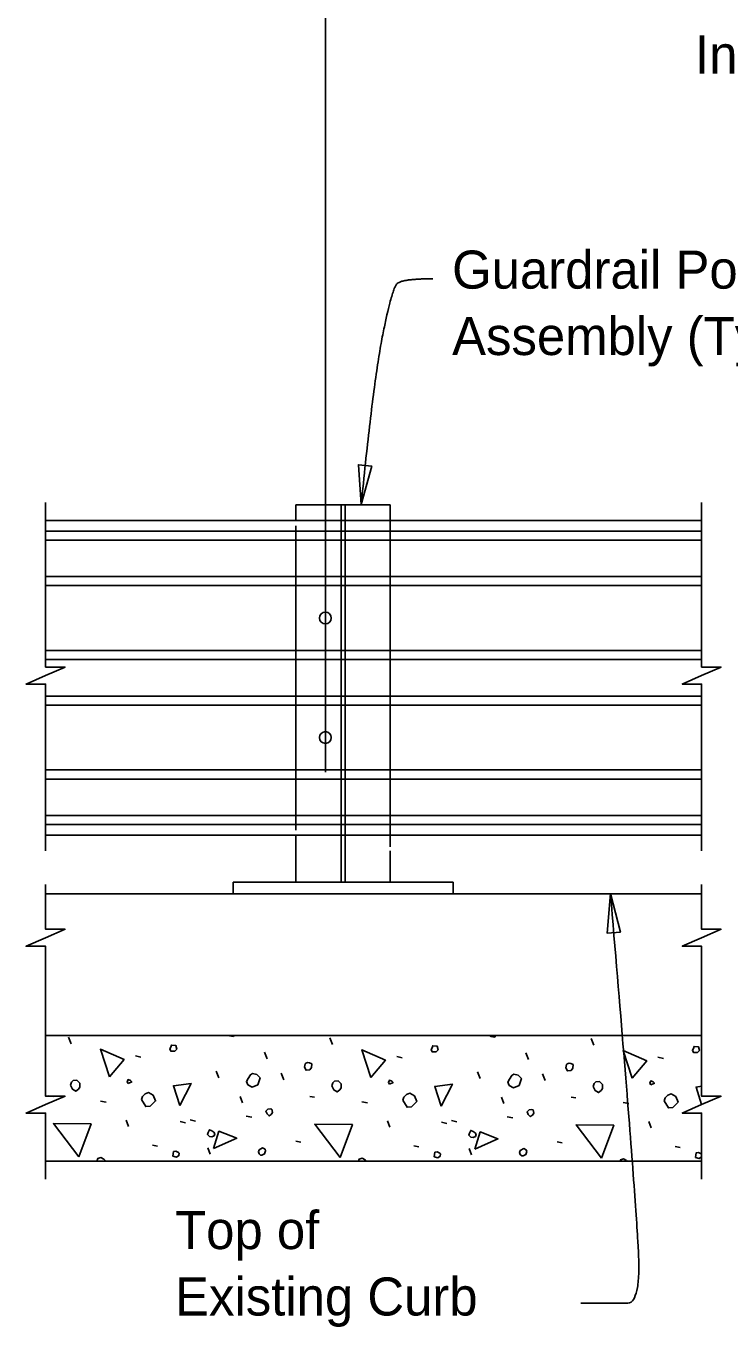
# Model space of a CAD drawing. Extents: x 21516.9 to 21589, y 56155.1 to 56195.
# Drawn here: x 21519.8 to 21523.53, y 56169.36 to 56176.26 of the extents above; entities that cross this region are included whole.
import ezdxf

# ---------------------------------------------------------------- set-up
doc = ezdxf.new("R2010")
doc.units = 0
for name, color, linetype in [('AdhocPoint_dp', 7, 'Continuous'), ('Border', 7, 'Continuous'), ('Patterning', 7, 'Continuous'), ('PlotBorder_dp', 7, 'Continuous'), ('TextMisc', 7, 'Continuous')]:
    doc.layers.add(name, color=color, linetype=linetype)

msp = doc.modelspace()

# ---------------------------------------------------------------- linework, layer by layer
at = {"layer": 'AdhocPoint_dp'}
for p, q in [((21523.3791, 56171.6541), (21519.9023, 56171.6541)), ((21519.9023, 56170.9041), (21523.3791, 56170.9041)), ((21523.3791, 56170.2374), (21519.9023, 56170.2374))]:
    msp.add_line(p, q, dxfattribs=at)
at = {"layer": 'Border'}
for p, q in [((21521.4686, 56171.7167), (21521.4686, 56173.7167)), ((21521.4894, 56171.7167), (21521.4894, 56173.7167)), ((21521.729, 56173.7167), (21521.729, 56171.9037)), ((21521.229, 56173.6048), (21521.229, 56171.9929))]:
    msp.add_line(p, q, dxfattribs=at)
at = {"layer": 'Patterning'}
for p, q in [((21521.229, 56173.7167), (21521.729, 56173.7167)), ((21521.229, 56173.7167), (21521.229, 56173.6334)), ((21519.9023, 56173.6333), (21523.3791, 56173.6333)), ((21519.9023, 56171.9666), (21523.3791, 56171.9666)), ((21521.229, 56171.9667), (21521.229, 56171.7167)), ((21521.729, 56171.8834), (21521.729, 56171.7167)), ((21520.8957, 56171.7167), (21522.0623, 56171.7167)), ((21520.8957, 56171.6542), (21520.8957, 56171.7167)), ((21521.229, 56171.7167), (21521.729, 56171.7167)), ((21522.0623, 56171.7167), (21522.0623, 56171.6542)), ((21520.8957, 56171.6542), (21522.0623, 56171.6542))]:
    msp.add_line(p, q, dxfattribs=at)
for centre in [(21521.3853, 56173.1166), (21521.3853, 56172.4835)]:
    msp.add_circle(centre, 0.0312, dxfattribs=at)
at = {"layer": 'PlotBorder_dp'}
msp.add_line((21521.3853, 56172.3005), (21521.3853, 56186.8174), dxfattribs=at)
for points in [[(21521.5749, 56173.7186), (21521.6306, 56173.9223), (21521.5604, 56173.9293)], [(21522.8958, 56171.6569), (21522.8782, 56171.4464), (21522.9485, 56171.4524)]]:
    msp.add_lwpolyline(points, close=True, dxfattribs=at)
for points in [[(21519.9023, 56171.8836), (21519.9023, 56172.7668), (21519.7989, 56172.7668), (21519.9023, 56172.8118), (21520.0056, 56172.8568), (21519.9023, 56172.8568), (21519.9023, 56173.7298)], [(21523.3791, 56171.8836), (21523.3791, 56172.7668), (21523.2758, 56172.7668), (21523.3791, 56172.8118), (21523.4824, 56172.8568), (21523.3791, 56172.8568), (21523.3791, 56173.7298)], [(21519.9023, 56170.9068), (21519.9023, 56171.3768), (21519.7989, 56171.3768), (21519.9023, 56171.4218), (21520.0056, 56171.4668), (21519.9023, 56171.4668), (21519.9023, 56171.7042)], [(21523.3791, 56170.9068), (21523.3791, 56171.3768), (21523.2758, 56171.3768), (21523.3791, 56171.4218), (21523.4824, 56171.4668), (21523.3791, 56171.4668), (21523.3791, 56171.7042)], [(21519.9023, 56170.1417), (21519.9023, 56170.4923), (21519.7989, 56170.4923), (21519.9023, 56170.5373), (21520.0056, 56170.5823), (21519.9023, 56170.5823), (21519.9023, 56170.9068)], [(21523.3791, 56170.1417), (21523.3791, 56170.4923), (21523.2758, 56170.4923), (21523.3791, 56170.5373), (21523.4824, 56170.5823), (21523.3791, 56170.5823), (21523.3791, 56170.9068)]]:
    msp.add_lwpolyline(points, dxfattribs=at)
for points in [[(21521.9541, 56174.9151), (21521.7906, 56174.9151), (21521.7383, 56174.8627), (21521.6402, 56174.3753), (21521.5749, 56173.7186)], [(21522.7388, 56169.4848), (21522.922, 56169.4848), (21523.0462, 56169.4848), (21523.0462, 56169.8773), (21522.8958, 56171.6569)]]:
    msp.add_open_spline(points, degree=2, dxfattribs=at)
at = {"layer": 'TextMisc'}
for p, q in [((21523.3791, 56173.5778), (21519.9023, 56173.5778)), ((21523.3791, 56173.5295), (21519.9023, 56173.5295)), ((21523.3791, 56173.3367), (21519.9023, 56173.3367)), ((21523.3791, 56173.2885), (21519.9023, 56173.2885)), ((21523.3791, 56172.9445), (21519.9023, 56172.9445)), ((21523.3791, 56172.8963), (21519.9023, 56172.8963)), ((21523.3791, 56172.7035), (21519.9023, 56172.7035)), ((21523.3791, 56172.6554), (21519.9023, 56172.6554)), ((21523.3791, 56172.3114), (21519.9023, 56172.3114)), ((21523.3791, 56172.2632), (21519.9023, 56172.2632)), ((21523.3791, 56172.0704), (21519.9023, 56172.0704)), ((21523.3791, 56172.0221), (21519.9023, 56172.0221)), ((21520.0378, 56170.8592), (21520.0236, 56170.8946)), ((21521.4224, 56170.8557), (21521.4083, 56170.891)), ((21522.8071, 56170.8521), (21522.793, 56170.8875)), ((21520.3783, 56170.7967), (21520.4066, 56170.7896)), ((21521.0766, 56170.7808), (21521.0624, 56170.8161)), ((21521.763, 56170.7932), (21521.7913, 56170.7861)), ((21522.4613, 56170.7773), (21522.4471, 56170.8126)), ((21523.1477, 56170.7896), (21523.176, 56170.7826)), ((21520.8203, 56170.68), (21520.8061, 56170.7154)), ((21521.1644, 56170.6683), (21521.1502, 56170.7036)), ((21522.2049, 56170.6765), (21522.1908, 56170.7118)), ((21522.549, 56170.6647), (21522.5349, 56170.7001)), ((21519.9176, 56170.5834), (21519.9423, 56170.5799)), ((21520.1933, 56170.5551), (21520.2234, 56170.5498)), ((21520.9458, 56170.5474), (21520.9334, 56170.581)), ((21521.3022, 56170.5799), (21521.327, 56170.5764)), ((21521.578, 56170.5516), (21521.6081, 56170.5463)), ((21522.3305, 56170.5439), (21522.3181, 56170.5775)), ((21522.6869, 56170.5764), (21522.7117, 56170.5728)), ((21522.9627, 56170.5481), (21522.9927, 56170.5428)), ((21520.9646, 56170.4756), (21520.9946, 56170.4703)), ((21520.3418, 56170.4208), (21520.3295, 56170.4544)), ((21520.6158, 56170.4473), (21520.6441, 56170.4402)), ((21520.6682, 56170.4573), (21520.6965, 56170.4502)), ((21521.7265, 56170.4173), (21521.7141, 56170.4508)), ((21522.0005, 56170.4438), (21522.0288, 56170.4367)), ((21522.0529, 56170.4538), (21522.0812, 56170.4467)), ((21522.3493, 56170.4721), (21522.3793, 56170.4668)), ((21523.1112, 56170.4137), (21523.0988, 56170.4473)), ((21521.228, 56170.343), (21521.2545, 56170.3377)), ((21522.6127, 56170.3395), (21522.6392, 56170.3342)), ((21520.4691, 56170.3218), (21520.4956, 56170.3165)), ((21520.7743, 56170.2747), (21520.7619, 56170.3083)), ((21521.8538, 56170.3183), (21521.8803, 56170.313)), ((21522.159, 56170.2712), (21522.1466, 56170.3047)), ((21523.2385, 56170.3147), (21523.265, 56170.3094))]:
    msp.add_line(p, q, dxfattribs=at)
for points in [[(21520.8761, 56170.9041), (21520.8768, 56170.9028), (21520.898, 56170.8992), (21520.9008, 56170.9041)], [(21522.2588, 56170.9041), (21522.2615, 56170.8992), (21522.2827, 56170.8957), (21522.2874, 56170.9041)], [(21520.2411, 56170.6842), (21520.1933, 56170.8309), (21520.3188, 56170.7761), (21520.2411, 56170.6842)], [(21520.5657, 56170.8214), (21520.5869, 56170.8214), (21520.5975, 56170.8321), (21520.5922, 56170.8515), (21520.5692, 56170.8533), (21520.5657, 56170.8427), (21520.5604, 56170.8338), (21520.5657, 56170.8214), (21520.5622, 56170.825)], [(21521.6257, 56170.6807), (21521.578, 56170.8274), (21521.7035, 56170.7726), (21521.6257, 56170.6807)], [(21521.9504, 56170.8179), (21521.9716, 56170.8179), (21521.9822, 56170.8285), (21521.9769, 56170.848), (21521.9539, 56170.8497), (21521.9504, 56170.8391), (21521.9451, 56170.8303), (21521.9504, 56170.8179), (21521.9468, 56170.8214)], [(21523.0104, 56170.6771), (21522.9627, 56170.8238), (21523.0882, 56170.769), (21523.0104, 56170.6771)], [(21523.3351, 56170.8144), (21523.3563, 56170.8144), (21523.3669, 56170.825), (21523.3616, 56170.8444), (21523.3386, 56170.8462), (21523.3351, 56170.8356), (21523.3298, 56170.8268), (21523.3351, 56170.8144), (21523.3315, 56170.8179)], [(21521.274, 56170.7355), (21521.2828, 56170.7195), (21521.3022, 56170.7213), (21521.3111, 56170.7337), (21521.3128, 56170.7531), (21521.3005, 56170.7584), (21521.2916, 56170.7602), (21521.281, 56170.7567), (21521.2775, 56170.7531), (21521.274, 56170.7355)], [(21522.6586, 56170.7319), (21522.6675, 56170.716), (21522.6869, 56170.7178), (21522.6958, 56170.7302), (21522.6975, 56170.7496), (21522.6851, 56170.7549), (21522.6763, 56170.7567), (21522.6657, 56170.7531), (21522.6622, 56170.7496), (21522.6586, 56170.7319)], [(21520.9741, 56170.6429), (21520.997, 56170.6305), (21521.0271, 56170.6429), (21521.0395, 56170.68), (21521.0218, 56170.6977), (21520.9988, 56170.703), (21520.9882, 56170.6959), (21520.9758, 56170.6765), (21520.967, 56170.6606), (21520.9741, 56170.6429)], [(21522.3587, 56170.6394), (21522.3817, 56170.627), (21522.4118, 56170.6394), (21522.4241, 56170.6765), (21522.4065, 56170.6942), (21522.3835, 56170.6995), (21522.3729, 56170.6924), (21522.3605, 56170.673), (21522.3517, 56170.657), (21522.3587, 56170.6394)], [(21520.0342, 56170.64), (21520.0448, 56170.6188), (21520.0625, 56170.6082), (21520.0767, 56170.6188), (21520.0837, 56170.6294), (21520.0837, 56170.6506), (21520.0678, 56170.6665), (21520.0484, 56170.6647), (21520.0395, 56170.6559), (21520.0342, 56170.64)], [(21520.3401, 56170.6488), (21520.3595, 56170.6577), (21520.3524, 56170.6647), (21520.3401, 56170.67), (21520.3348, 56170.6577), (21520.3401, 56170.6488)], [(21520.6134, 56170.5333), (21520.5798, 56170.6376), (21520.6735, 56170.65), (21520.6134, 56170.5333)], [(21521.4189, 56170.6365), (21521.4295, 56170.6152), (21521.4472, 56170.6046), (21521.4613, 56170.6152), (21521.4684, 56170.6259), (21521.4684, 56170.6471), (21521.4525, 56170.663), (21521.4331, 56170.6612), (21521.4242, 56170.6524), (21521.4189, 56170.6365)], [(21521.7247, 56170.6453), (21521.7442, 56170.6541), (21521.7371, 56170.6612), (21521.7247, 56170.6665), (21521.7194, 56170.6541), (21521.7247, 56170.6453)], [(21521.9981, 56170.5298), (21521.9645, 56170.6341), (21522.0582, 56170.6464), (21521.9981, 56170.5298)], [(21522.8036, 56170.6329), (21522.8142, 56170.6117), (21522.8319, 56170.6011), (21522.846, 56170.6117), (21522.8531, 56170.6223), (21522.8531, 56170.6435), (21522.8372, 56170.6594), (21522.8177, 56170.6577), (21522.8089, 56170.6488), (21522.8036, 56170.6329)], [(21523.1094, 56170.6418), (21523.1289, 56170.6506), (21523.1218, 56170.6577), (21523.1094, 56170.663), (21523.1041, 56170.6506), (21523.1094, 56170.6418)], [(21523.3791, 56170.5377), (21523.3492, 56170.6305), (21523.3791, 56170.6345)], [(21520.4108, 56170.564), (21520.4337, 56170.5269), (21520.4567, 56170.5286), (21520.4656, 56170.5375), (21520.485, 56170.5569), (21520.4726, 56170.587), (21520.4479, 56170.6011), (21520.4302, 56170.594), (21520.4161, 56170.5799), (21520.4108, 56170.564)], [(21521.7954, 56170.5604), (21521.8184, 56170.5233), (21521.8414, 56170.5251), (21521.8502, 56170.5339), (21521.8697, 56170.5534), (21521.8573, 56170.5834), (21521.8326, 56170.5976), (21521.8149, 56170.5905), (21521.8007, 56170.5764), (21521.7954, 56170.5604)], [(21523.1801, 56170.5569), (21523.2031, 56170.5198), (21523.2261, 56170.5216), (21523.2349, 56170.5304), (21523.2544, 56170.5498), (21523.242, 56170.5799), (21523.2172, 56170.594), (21523.1996, 56170.587), (21523.1854, 56170.5728), (21523.1801, 56170.5569)], [(21521.076, 56170.488), (21521.0866, 56170.4774), (21521.0972, 56170.4844), (21521.1042, 56170.495), (21521.1007, 56170.5127), (21521.0919, 56170.5145), (21521.0795, 56170.5127), (21521.0689, 56170.5021), (21521.076, 56170.488)], [(21522.4606, 56170.4844), (21522.4712, 56170.4738), (21522.4819, 56170.4809), (21522.4889, 56170.4915), (21522.4854, 56170.5092), (21522.4766, 56170.5109), (21522.4642, 56170.5092), (21522.4536, 56170.4986), (21522.4606, 56170.4844)], [(21520.0784, 56170.2599), (21519.9441, 56170.4367), (21520.1438, 56170.4349), (21520.0784, 56170.2599)], [(21520.7708, 56170.3689), (21520.7831, 56170.3671), (21520.7955, 56170.3724), (21520.7991, 56170.383), (21520.7937, 56170.3919), (21520.7831, 56170.399), (21520.7708, 56170.4043), (21520.7637, 56170.3901), (21520.7602, 56170.3795), (21520.7708, 56170.3689)], [(21521.4631, 56170.2564), (21521.3288, 56170.4332), (21521.5285, 56170.4314), (21521.4631, 56170.2564)], [(21522.8478, 56170.2529), (21522.7134, 56170.4296), (21522.9132, 56170.4279), (21522.8478, 56170.2529)], [(21520.7931, 56170.3041), (21520.8214, 56170.396), (21520.9151, 56170.3589), (21520.7931, 56170.3041)], [(21522.1554, 56170.3654), (21522.1678, 56170.3636), (21522.1802, 56170.3689), (21522.1837, 56170.3795), (21522.1784, 56170.3883), (21522.1678, 56170.3954), (21522.1554, 56170.4007), (21522.1484, 56170.3866), (21522.1448, 56170.376), (21522.1554, 56170.3654)], [(21522.1778, 56170.3006), (21522.2061, 56170.3925), (21522.2998, 56170.3554), (21522.1778, 56170.3006)], [(21520.5769, 56170.2635), (21520.5964, 56170.2582), (21520.6088, 56170.267), (21520.6105, 56170.2794), (21520.607, 56170.2829), (21520.5928, 56170.29), (21520.5805, 56170.2882), (21520.5787, 56170.2758), (21520.5769, 56170.2635)], [(21521.0406, 56170.2688), (21521.0477, 56170.2688), (21521.0618, 56170.2758), (21521.0671, 56170.2917), (21521.0654, 56170.3006), (21521.0512, 56170.3077), (21521.0335, 56170.297), (21521.03, 56170.2864), (21521.0335, 56170.2758), (21521.0406, 56170.2688)], [(21521.9616, 56170.2599), (21521.9811, 56170.2546), (21521.9934, 56170.2635), (21521.9952, 56170.2758), (21521.9917, 56170.2794), (21521.9775, 56170.2864), (21521.9652, 56170.2847), (21521.9634, 56170.2723), (21521.9616, 56170.2599)], [(21522.4253, 56170.2652), (21522.4324, 56170.2652), (21522.4465, 56170.2723), (21522.4518, 56170.2882), (21522.45, 56170.297), (21522.4359, 56170.3041), (21522.4182, 56170.2935), (21522.4147, 56170.2829), (21522.4182, 56170.2723), (21522.4253, 56170.2652)], [(21523.3791, 56170.2731), (21523.3763, 56170.2758), (21523.3622, 56170.2829), (21523.3498, 56170.2811), (21523.3481, 56170.2688), (21523.3463, 56170.2564)], [(21523.3463, 56170.2564), (21523.3657, 56170.2511), (21523.3781, 56170.2599), (21523.3791, 56170.2669)], [(21520.2195, 56170.2374), (21520.2198, 56170.2387), (21520.211, 56170.2476), (21520.1951, 56170.2564), (21520.1792, 56170.2511), (21520.1746, 56170.2374)], [(21521.6023, 56170.2374), (21521.5957, 56170.244), (21521.5798, 56170.2529), (21521.5639, 56170.2476), (21521.5605, 56170.2374)], [(21522.9834, 56170.2374), (21522.9804, 56170.2405), (21522.9645, 56170.2493), (21522.9485, 56170.244), (21522.9464, 56170.2374)]]:
    msp.add_lwpolyline(points, dxfattribs=at)

# ---------------------------------------------------------------- texts
at = {"layer": 'PlotBorder_dp'}
for s, p in [('Index 460-470, Sheet 2) (Typ.)', (21523.3441, 56176.0033)), ('Guardrail Post ', (21522.0566, 56174.863)), ('Assembly (Typ.)', (21522.0566, 56174.511)), ('Top of ', (21520.5887, 56169.7716)), ('Existing Curb', (21520.5887, 56169.4196))]:
    msp.add_text(s, height=0.2016, dxfattribs=at).set_placement(p)

doc.saveas('drawing.dxf')
